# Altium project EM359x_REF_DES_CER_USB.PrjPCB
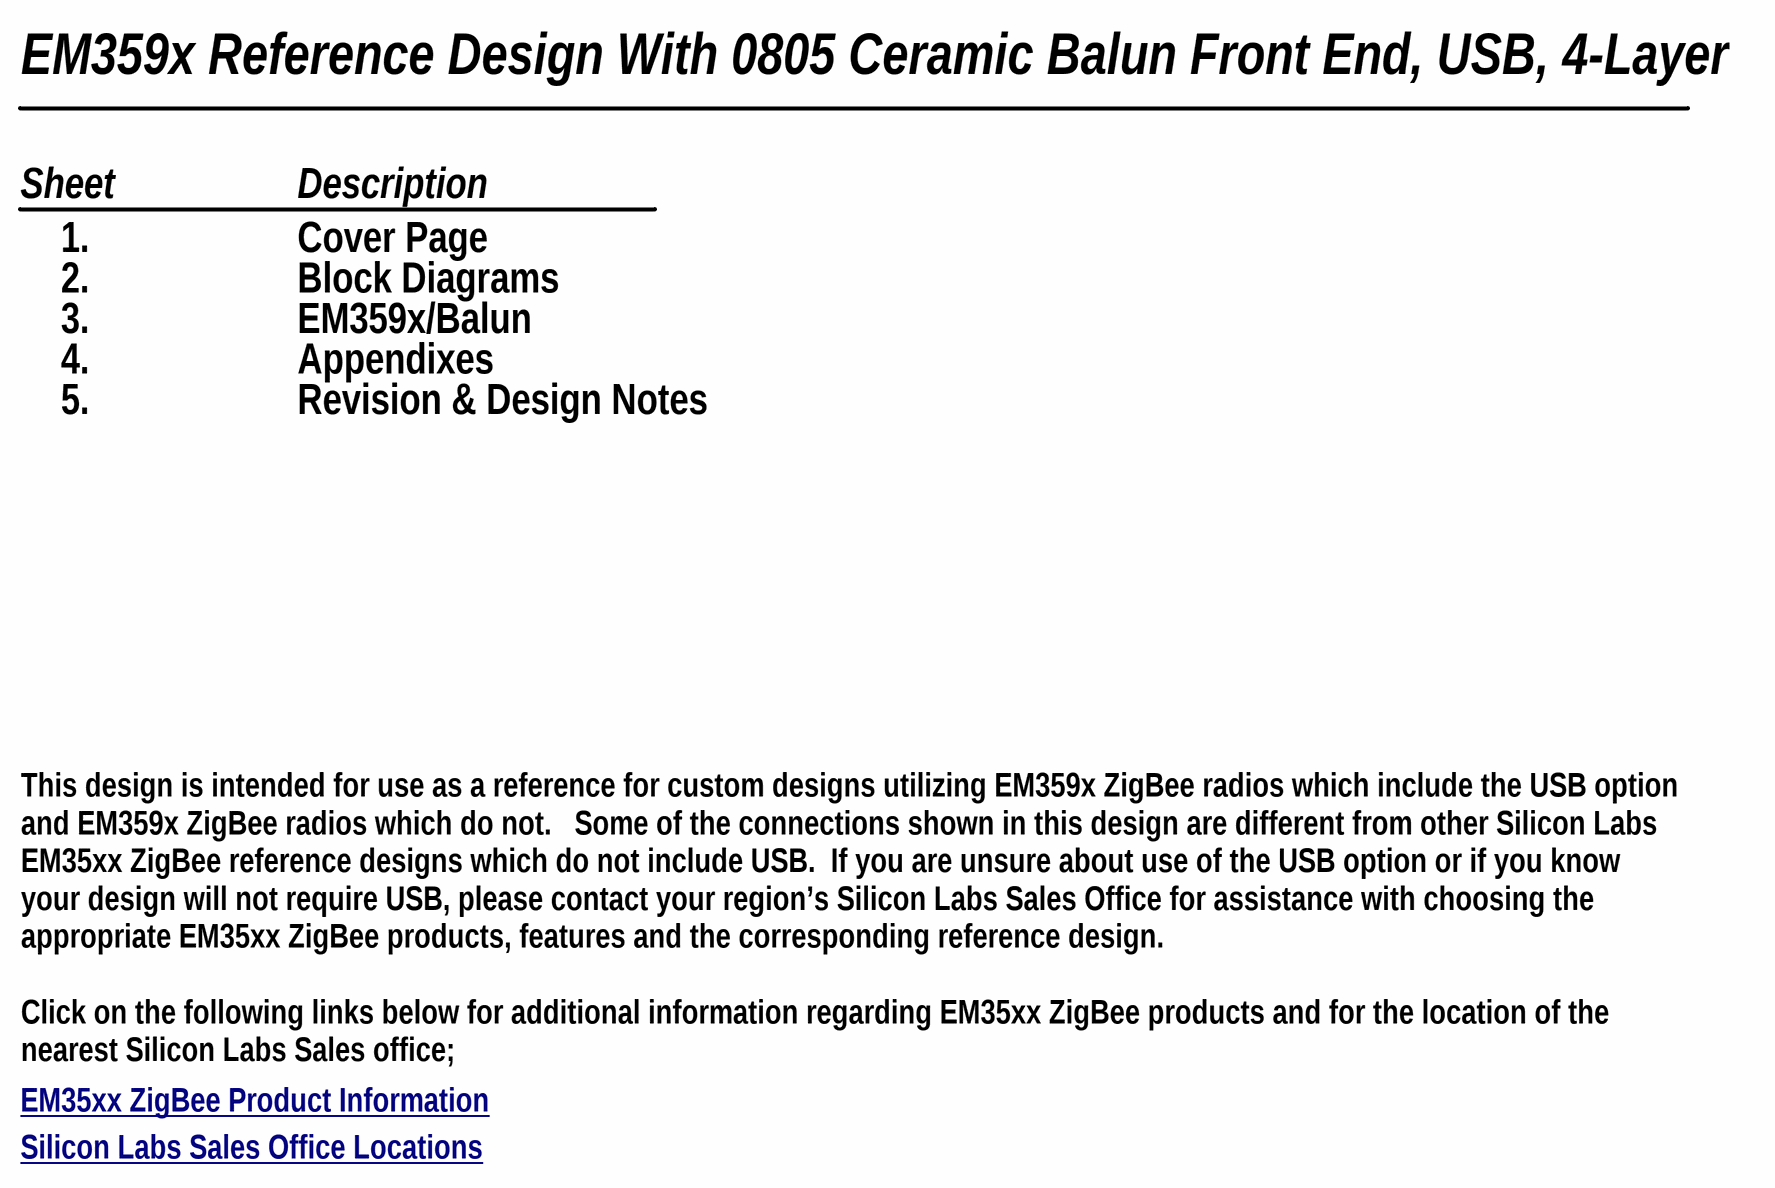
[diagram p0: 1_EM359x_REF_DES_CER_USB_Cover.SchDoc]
Board No: EM359x_REF_DES_CER_USB; Board Rev: A0; ClassName: PCB Only; Company Address 1: 343 Congress St; Company Address 2: 4th Floor; Company Address 3: Boston, MA 02210; Company Design Group: MCU & Wireless WMN Support; Company Tel: 617-951-0200; Company Web Site: www.silabs.com; Title: EM359x Ref Des, Ceramic Balun, USB, 4-layer
5 sheets, 70 parts. Net scope: global (net labels, ports and power ports of the same name join across sheets).
Board file: EM359x_REF_DES_CER_USB.PcbDoc
Sheets:
  1_EM359x_REF_DES_CER_USB_Cover.SchDoc
  2_EM359x_REF_DES_CER_USB_Block.SchDoc
  3_EM359x_REF_DES_CER_USB_Main.SchDoc
  4_EM359x_REF_DES_CER_USB_App.SchDoc
  5_EM359x_REF_DES_CER_USB_Rev_Notes.SchDoc

## Sheet 1_EM359x_REF_DES_CER_USB_Cover.SchDoc: EM359x/0805 Ceramic Balun W/USB Reference Design
size C; IsUserConfigurable: (Sheet Name); Organization: MCU & Wireless WMN Support; Address1: 343 Congress Street, 4th Fl,; Address2: Boston, MA 02210, USA; Address3: www.silabs.com; Address4: 617-951-0200; DocumentNumber: 130-0859-001; Revision: A0; SheetNumber: 1; SheetTotal: 5; SheetSize: C

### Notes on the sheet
- EM359x Reference Design With 0805 Ceramic Balun Front End, USB, 4-Layer
- Sheet
- 1.
- Description
- Cover Page
- 2.
- Block Diagrams
- 3.
- 4.
- EM359x/Balun
- Appendixes
- 5.
- Revision & Design Notes
- This design is intended for use as a reference for custom designs utilizing EM359x ZigBee radios which include the USB option and EM359x ZigBee radios which do not.   Some of the connections shown in this design are different from other Silicon Labs EM35xx ZigBee reference designs which do not include USB.  If you are unsure about use of the USB option or if you know your design will not require USB, please contact your region’s Silicon Labs Sales Office for assistance with choosing the appropriate EM35xx ZigBee products, features and the corresponding reference design.
  Click on the following links below for additional information regarding EM35xx ZigBee products and for the location of the nearest Silicon Labs Sales office;
- EM35xx ZigBee Product Information <http://www.silabs.com/products/wireless/zigbee/Pages/default.aspx>
- Silicon Labs Sales Office Locations <http://www.silabs.com/buysample/pages/contact-sales.aspx>

## Sheet 2_EM359x_REF_DES_CER_USB_Block.SchDoc: EM359x/0805 Ceramic Balun W/USB Reference Design
size C; Organization: MCU & Wireless WMN Support; Address1: 343 Congress Street, 4th Fl,; Address2: Boston, MA 02210, USA; Address3: www.silabs.com; Address4: 617-951-0200; DocumentNumber: 130-0859-001; Revision: A0; SheetNumber: 2; SheetTotal: 5; SheetSize: C
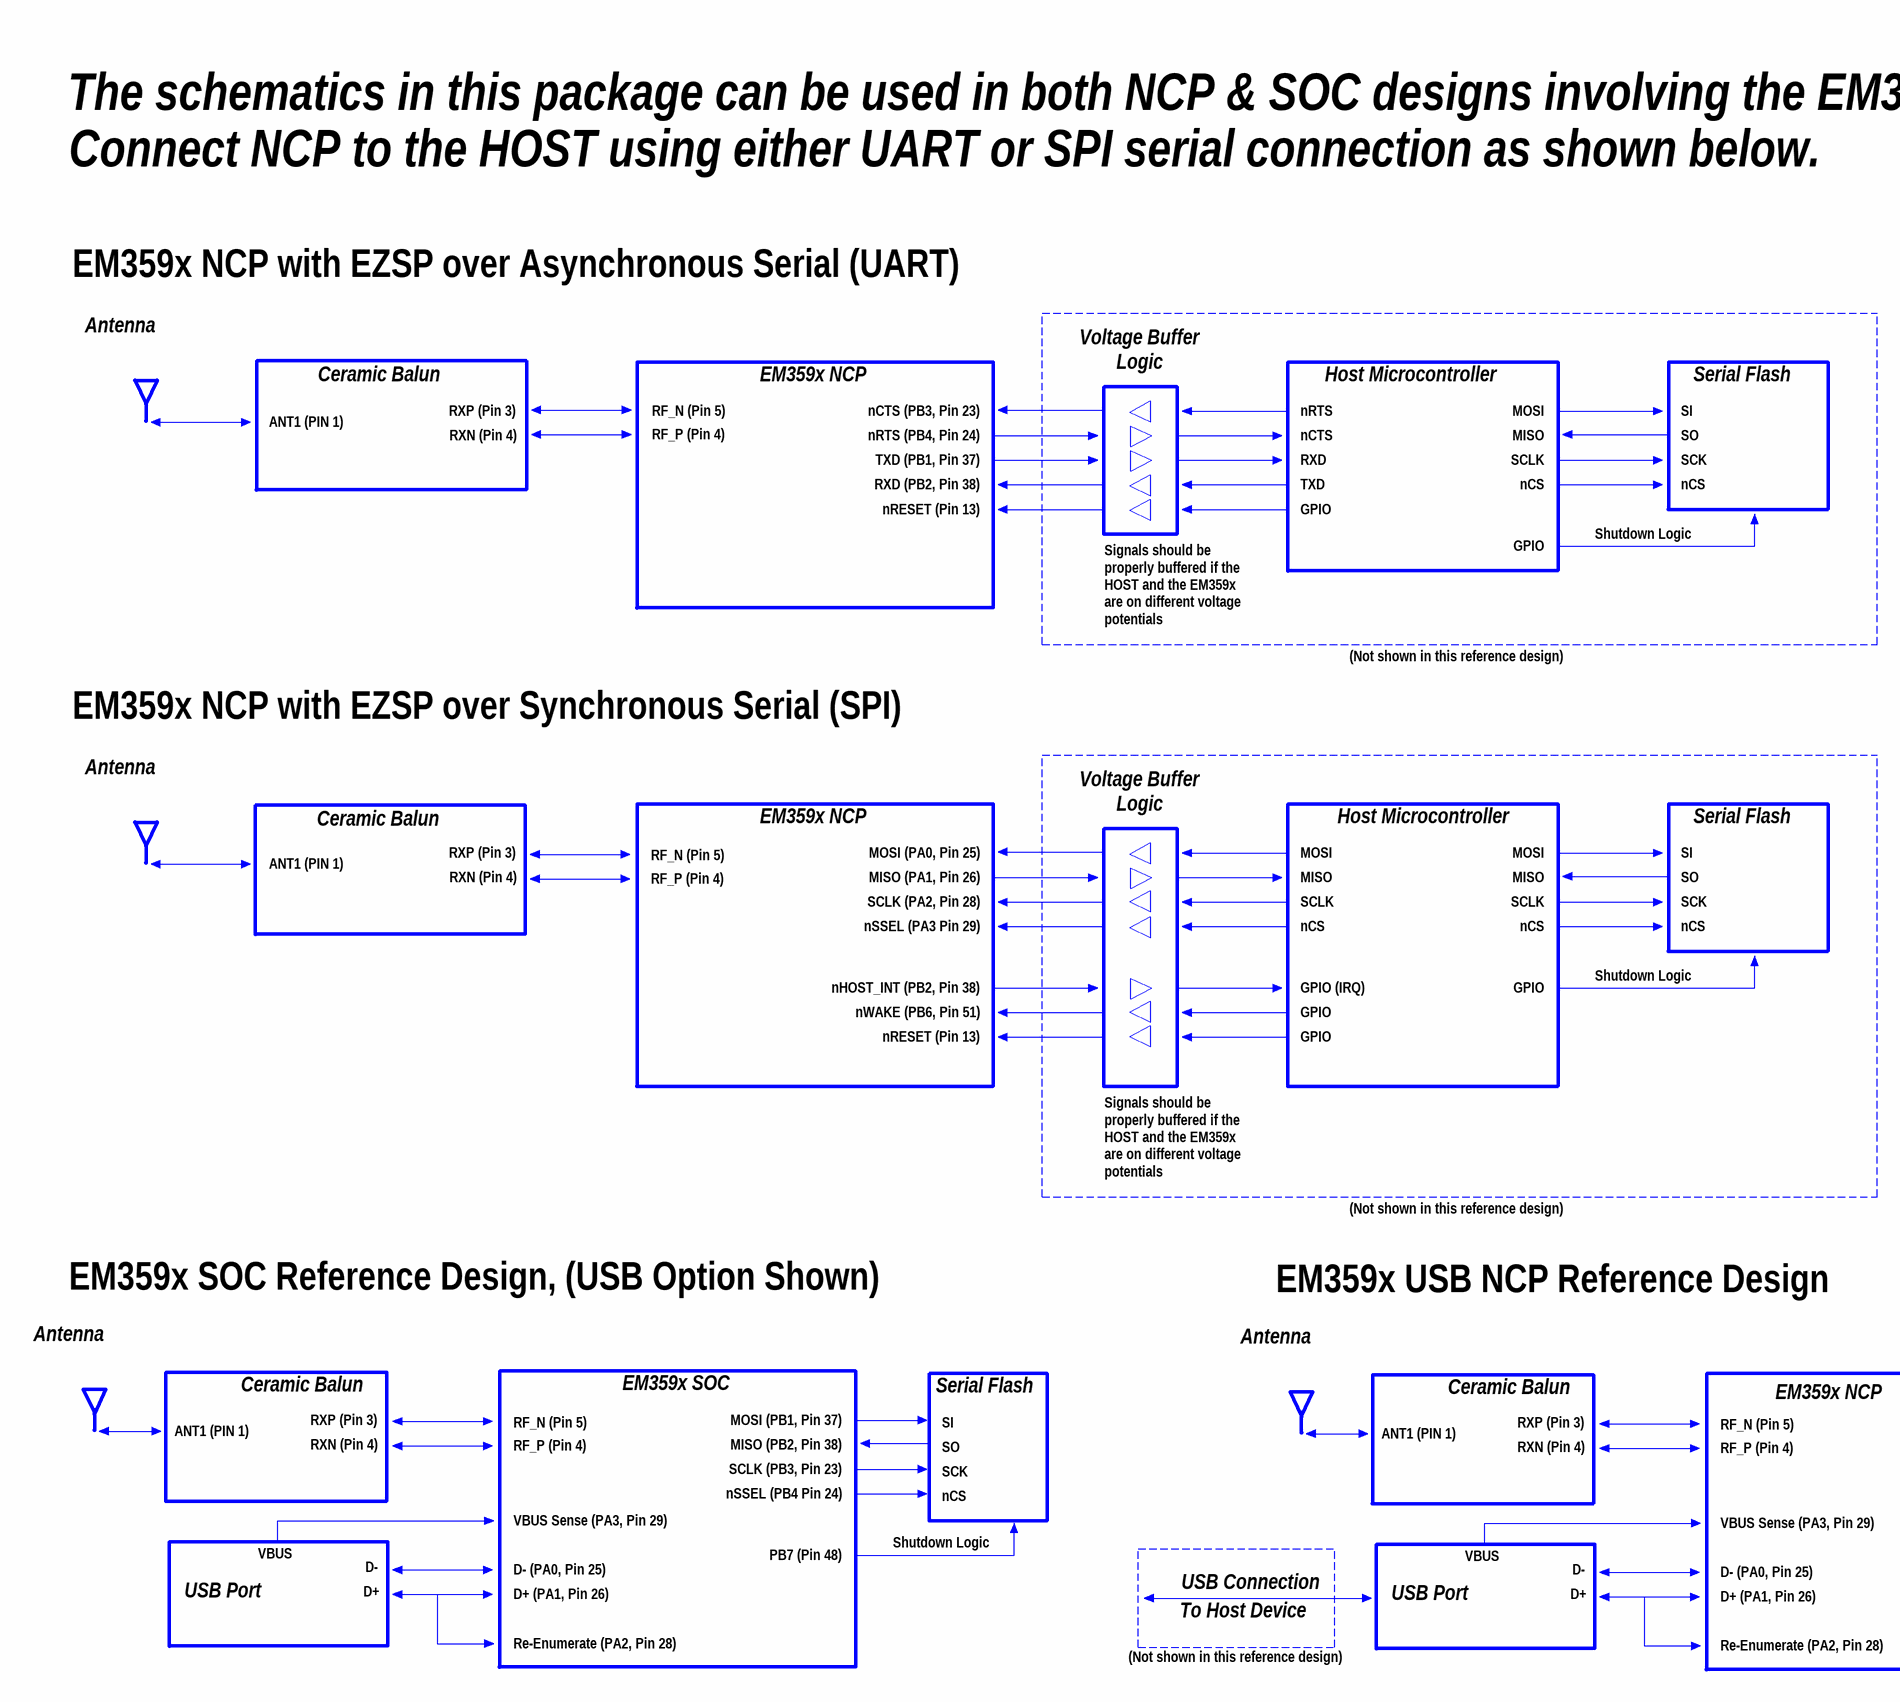
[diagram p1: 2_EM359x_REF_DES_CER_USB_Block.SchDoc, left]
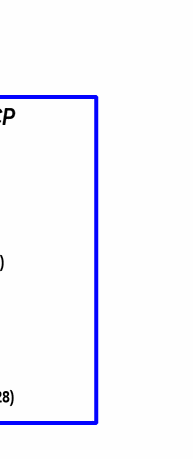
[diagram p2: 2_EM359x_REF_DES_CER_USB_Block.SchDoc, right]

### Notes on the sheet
- The schematics in this package can be used in both NCP & SOC designs involving the EM359x.
- Connect NCP to the HOST using either UART or SPI serial connection as shown below.
- EM359x NCP with EZSP over Asynchronous Serial (UART)
- Antenna
- Ceramic Balun
- EM359x NCP
- Voltage Buffer
- Logic
- Host Microcontroller
- Serial Flash
- ANT1 (PIN 1)
- RXP (Pin 3)
- RXN (Pin 4)
- RF_N (Pin 5)
- RF_P (Pin 4)
- nCTS (PB3, Pin 23)
- nRTS (PB4, Pin 24)
- nRTS
- nCTS
- MOSI
- MISO
- SI
- SO
- TXD (PB1, Pin 37)
- RXD (PB2, Pin 38)
- nRESET (Pin 13)
- RXD
- TXD
- GPIO
- SCLK
- nCS
- SCK
- Shutdown Logic
- Signals should be properly buffered if the HOST and the EM359x are on different voltage potentials
- (Not shown in this reference design)
- EM359x NCP with EZSP over Synchronous Serial (SPI)
- MOSI (PA0, Pin 25)
- MISO (PA1, Pin 26)
- SCLK (PA2, Pin 28)
- nSSEL (PA3 Pin 29)
- nHOST_INT (PB2, Pin 38)
- GPIO (IRQ)
- nWAKE (PB6, Pin 51)
- EM359x SOC Reference Design, (USB Option Shown)
- EM359x USB NCP Reference Design
- EM359x SOC
- MOSI (PB1, Pin 37)
- MISO (PB2, Pin 38)
- SCLK (PB3, Pin 23)
- nSSEL (PB4 Pin 24)
- VBUS
- VBUS Sense (PA3, Pin 29)
- PB7 (Pin 48)
- USB Port
- D-
- D+
- D- (PA0, Pin 25)
- D+ (PA1, Pin 26)
- To Host Device
- USB Connection
- Re-Enumerate (PA2, Pin 28)

## Sheet 3_EM359x_REF_DES_CER_USB_Main.SchDoc: EM359x/0805 Ceramic Balun W/USB Reference Design
size C; Organization: MCU & Wireless WMN Support; Address1: 343 Congress Street, 4th Fl,; Address2: Boston, MA 02210, USA; Address3: www.silabs.com; Address4: 617-951-0200; DocumentNumber: 130-0859-001; Revision: A0; SheetNumber: 3; SheetTotal: 5; SheetSize: C
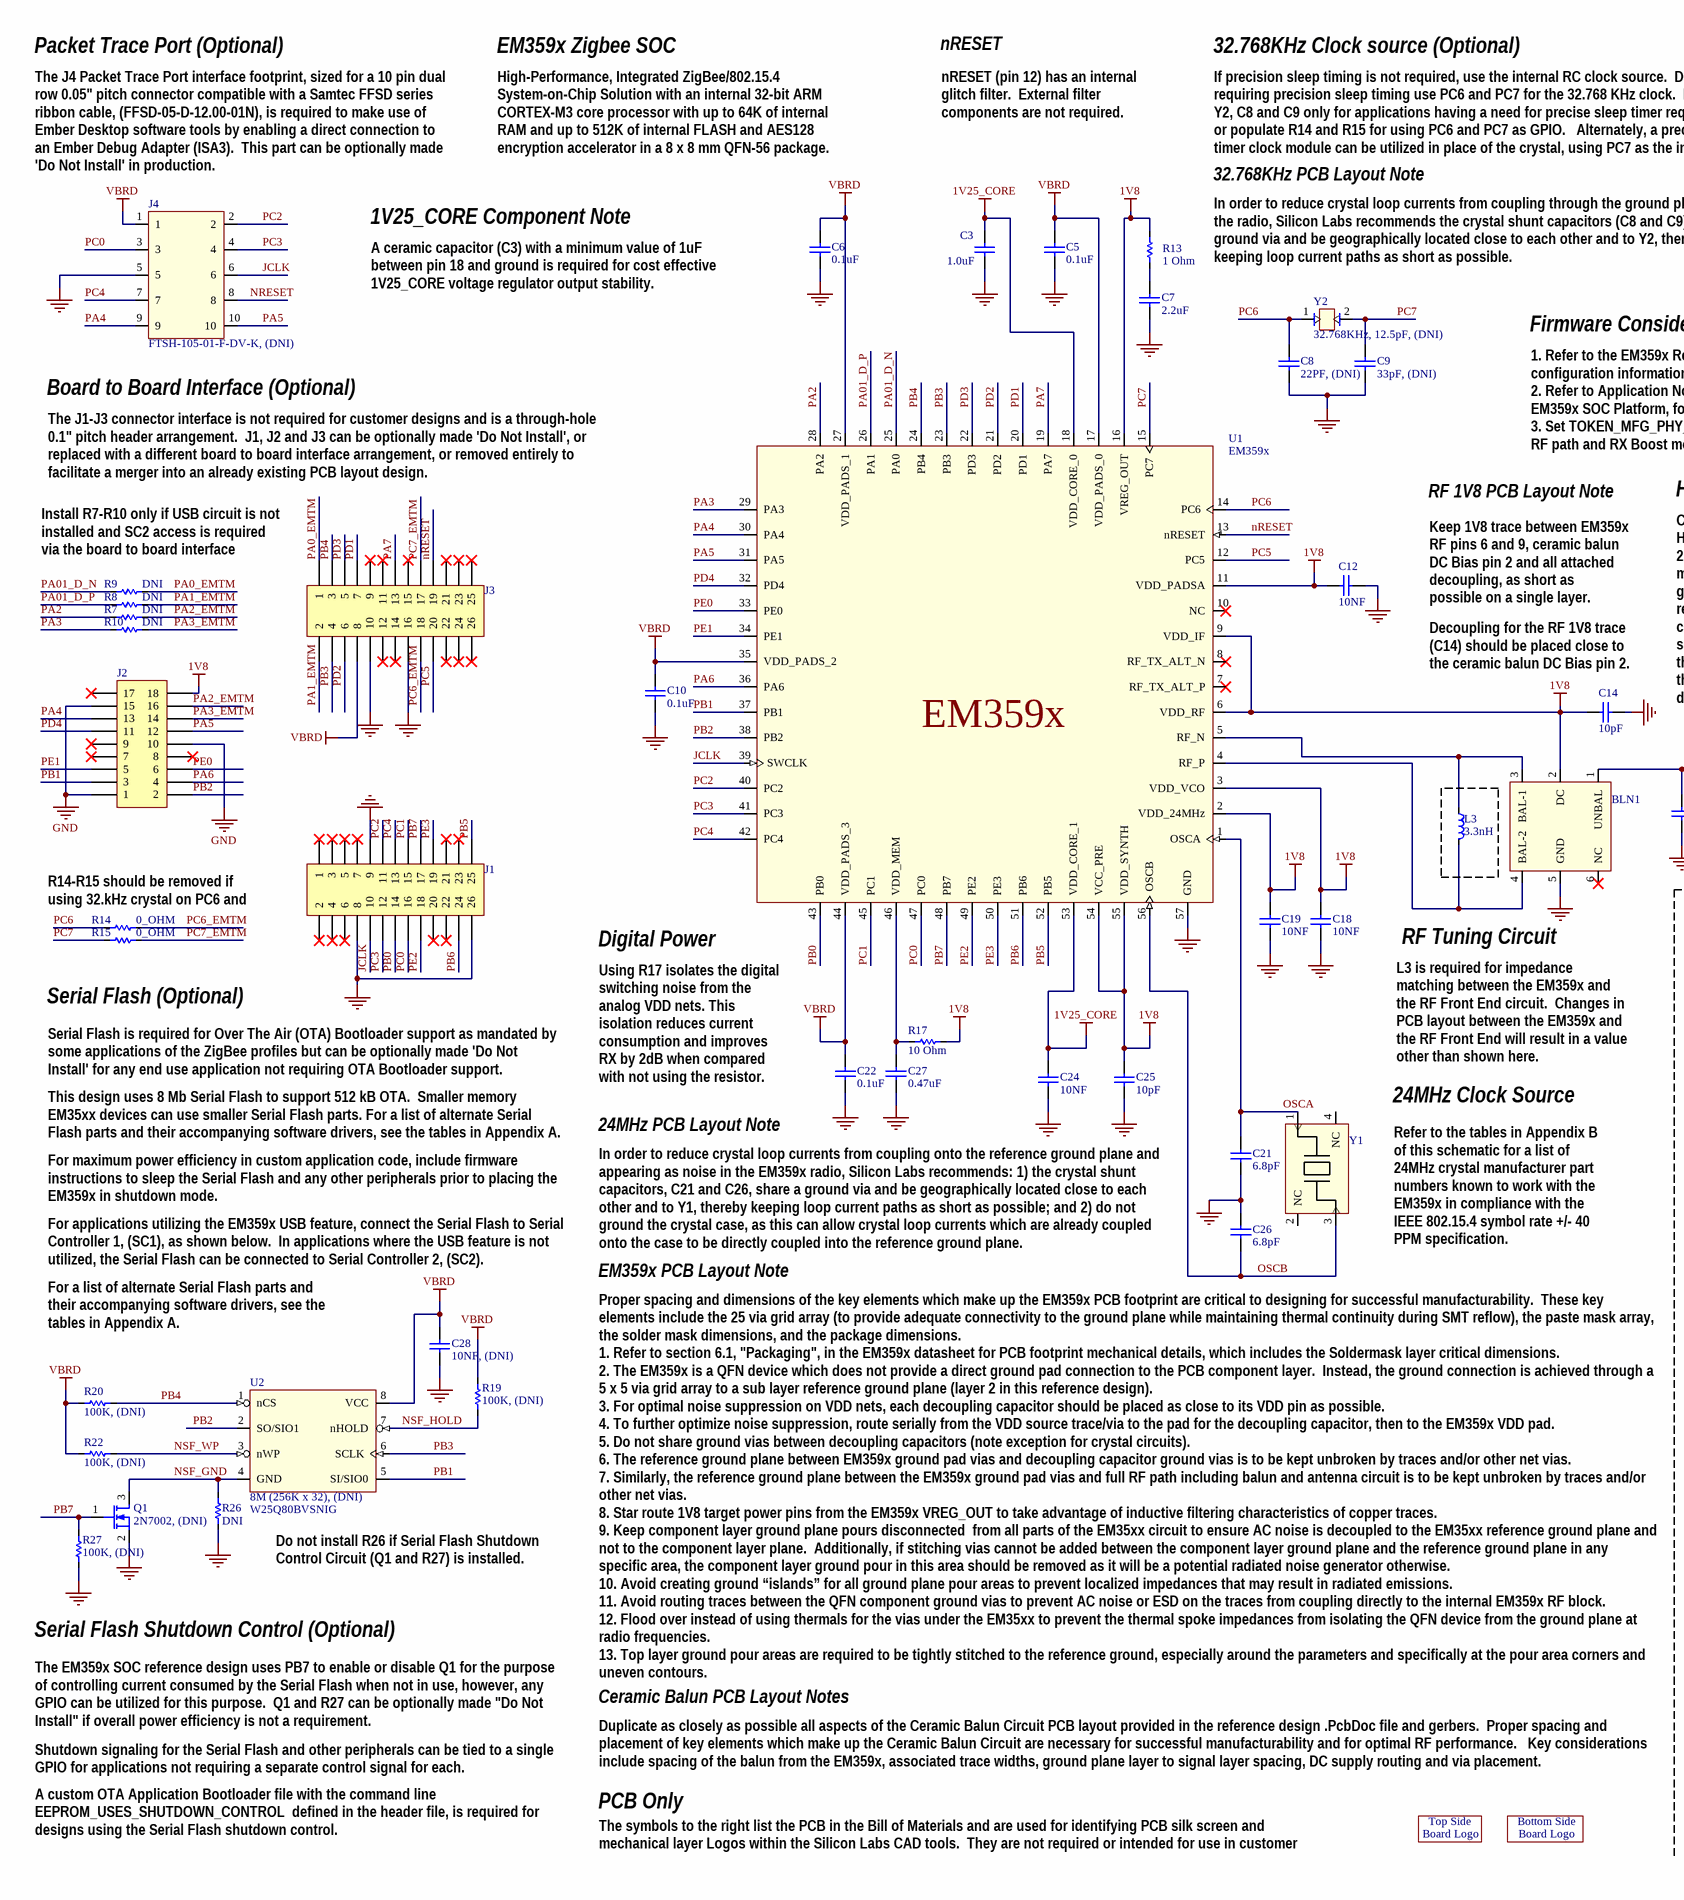
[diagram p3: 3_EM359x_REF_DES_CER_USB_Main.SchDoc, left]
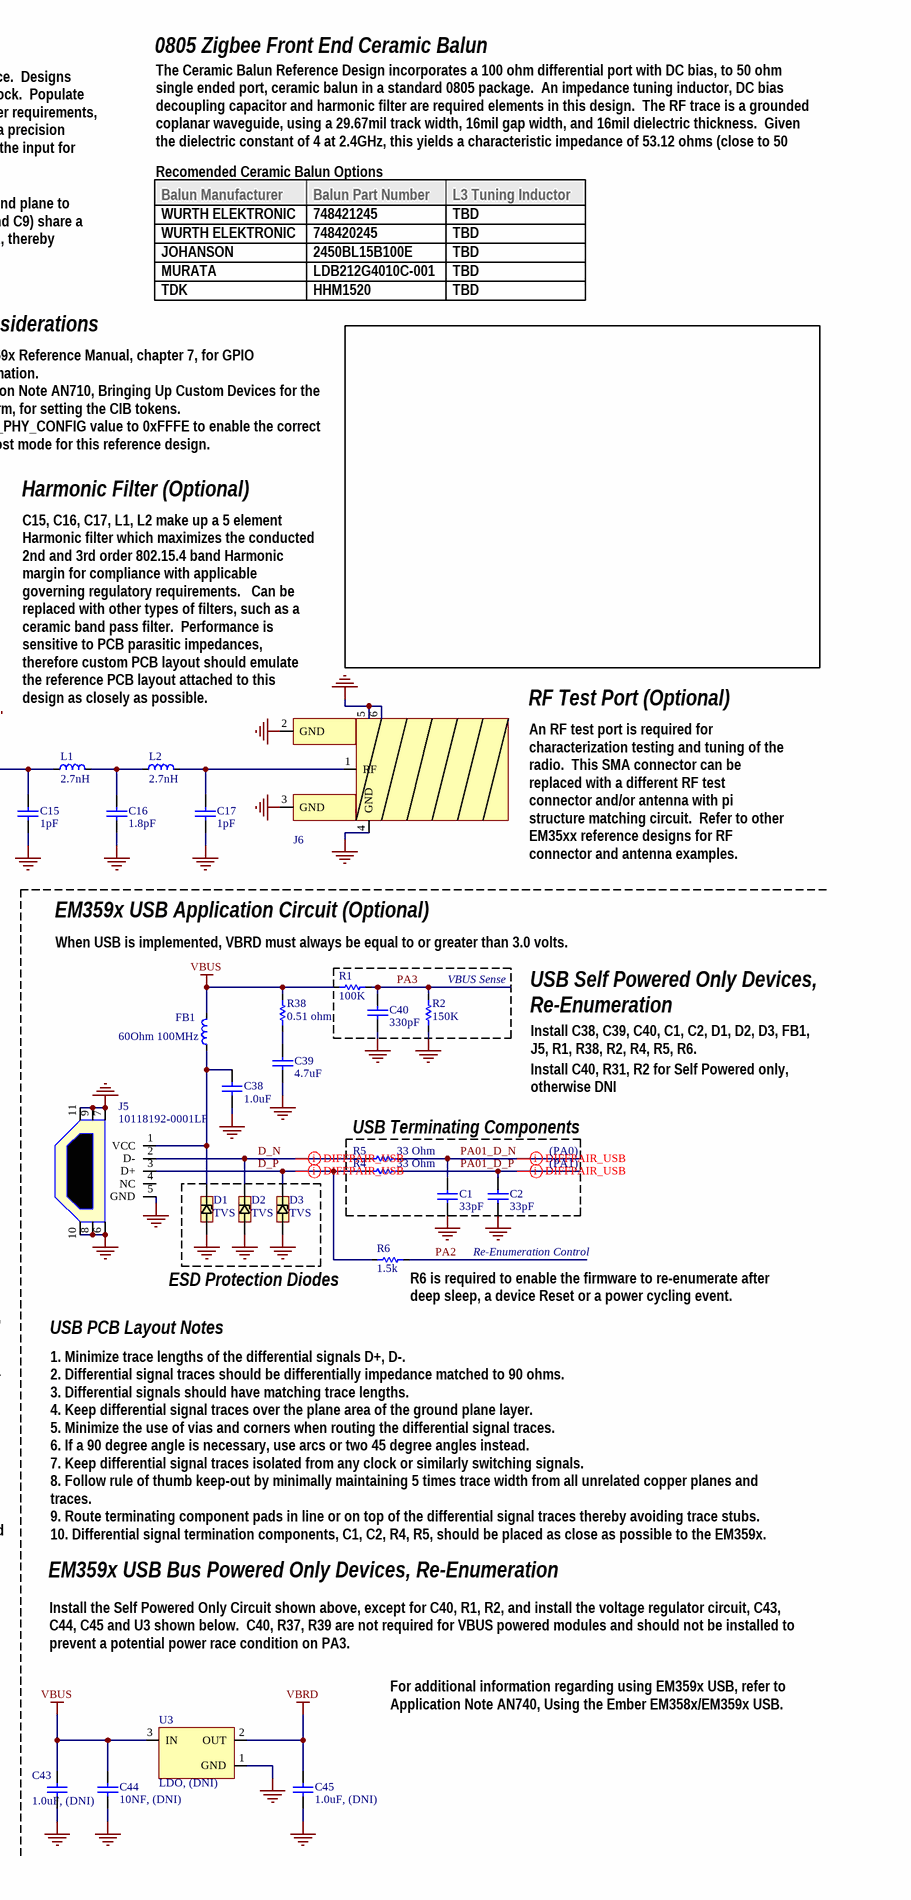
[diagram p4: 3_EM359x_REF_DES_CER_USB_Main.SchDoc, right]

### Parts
BLN1  CHIP MULTILAYER CERAMIC, 2.4 GHZ. 50/100 Ohm  [BLN_0805]  (value not drawn)
C1  33pF  [C_0402]
C2  33pF  [C_0402]
C3  1.0uF  [C_0603]
C5  0.1uF  [C_0402]
C6  0.1uF  [C_0402]
C7  2.2uF  [C_0603]
C8  22PF, (DNI)  [C_0402]
C9  33pF, (DNI)  [C_0402]
C10  0.1uF  [C_0402]
C12  10NF  [C_0402]
C14  10pF  [C_0402]
C15  1pF  [C_0402]
C16  1.8pF  [C_0402]
C17  1pF  [C_0402]
C18  10NF  [C_0402]
C19  10NF  [C_0402]
C21  6.8pF  [C_0402]
C22  0.1uF  [C_0402]
C24  10NF  [C_0402]
C25  10pF  [C_0402]
C26  6.8pF  [C_0402]
C27  0.47uF  [C_0402]
C28  10NF, (DNI)  [C_0402]
C38  1.0uF  [C_0603]
C39  4.7uF  [C_0603]
C40  330pF  [C_0402]
C43  1.0uF, (DNI)  [C_0603]
C44  10NF, (DNI)  [C_0402]
C45  1.0uF, (DNI)  [C_0603]
D1  TVS  [TVS_0402]
D2  TVS  [TVS_0402]
D3  TVS  [TVS_0402]
FB1  60Ohm 100MHz  [L_0603]
J1  HEADER 13 x 2  [HEADER-26-SUL-THRU-SHRD]  (value not drawn)
J2  HEADER 9 x 2  [HEADER-18-SUL-THRU-SHRD]  (value not drawn)
J3  HEADER 13 x 2  [HEADER-26-SUL-THRU-SHRD]  (value not drawn)
J4  FTSH-105-01-F-DV-K, (DNI)  [610-0019-000]
J5  10118192-0001LF  [FCI_10118192-0001LF]
J6  SMA_JACK_SMD  [SMA_WIDE]  (value not drawn)
L1  2.7nH  [L_0402]
L2  2.7nH  [L_0402]
L3  3.3nH  [L_0603]
PCB1  EM359x Ceramic Balun 4 Layer Reference Design w/USB, SMA Connector, Corporate Logo  [710-0859-001]  (value not drawn)
PCB2  Bottom Silk Screen ID and RoHS Text  [710-0859-001_ROHS]  (value not drawn)  (no BOM)
Q1  2N7002, (DNI)  [SOT23-3L]
R1  100K  [R_0402]
R2  150K  [R_0402]
R4  33 Ohm  [R_0402]
R5  33 Ohm  [R_0402]
R6  1.5k  [R_0402]
R7  DNI  [R_0402]
R8  DNI  [R_0402]
R9  DNI  [R_0402]
R10  DNI  [R_0402]
R13  1 Ohm  [R_0402]
R14  0_OHM  [R_0402]
R15  0_OHM  [R_0402]
R17  10 Ohm  [R_0402]
R19  100K, (DNI)  [R_0402]
R20  100K, (DNI)  [R_0402]
R22  100K, (DNI)  [R_0402]
R26  value DNI  [R_0402]  (hidden comment: EMBER_RESISTOR.1)
R27  100K, (DNI)  [R_0402]
R38  0.51 ohm  [R_0402]
U1  EM359x  [EM359X]
U2  8M (256K x 32), (DNI)  PART_NUMBER: W25Q80BVSNIG  [SOIC127P600-8M]
U3  LDO, (DNI)  [TSOP95P280X90-3N]
Y1  24MHz  [ABM8]  (value not drawn)
Y2  32.768KHz, 12.5pF, (DNI)  [IL3X]

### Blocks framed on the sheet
VBUS Sense: C40 R1 R2
USB Terminating Components: C1 C2 R4 R5

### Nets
1V8: BLN1.2(DC) C12.1 C14.2 C18.1 C19.1 C25.1 J2.18 R13.1 R17.1 U1.2(VDD_24MHz) U1.3(VDD_VCO) U1.6(VDD_RF) U1.9(VDD_IF) U1.11(VDD_PADSA) U1.16(VREG_OUT) U1.54(VCC_PRE) U1.55(VDD_SYNTH)
1V25_CORE: C3.1 C24.1 U1.18(VDD_CORE_0) U1.53(VDD_CORE_1)
GND: BLN1.5(GND) C1.1 C2.1 C3.2 C5.2 C6.2 C7.2 C8.2 C9.2 C10.2 C12.2 C14.1 C15.2 C16.2 C17.2 C18.2 C19.2 C21.2 C22.2 C24.2 C25.2 C26.2 C27.2 C28.2 C38.2 C39.2 C40.2 C43.2 C44.2 C45.2 D1.1 D2.1 D3.1 J1.8 J1.9 J1.26 J2.1 J2.10 J2.15 J3.10 J3.16 J4.5 J5.5(GND) J5.6 J5.7 J5.8 J5.9 J5.10 J5.11 J6.2(GND) J6.3(GND) J6.4(GND) J6.5(GND) J6.6(GND) Q1.2(S) R2.2 R26.2 R27.2 U1.57(GND) U3.1(GND)
VBRD: C5.1 C6.1 C10.1 C22.1 C28.1 C45.1 J3.8 J4.1 R19.2 R20.2 R22.2 U1.17(VDD_PADS_0) U1.27(VDD_PADS_1) U1.35(VDD_PADS_2) U1.44(VDD_PADS_3) U2.8(VCC) U3.2(OUT)
VBUS: C43.1 C44.1 FB1.2 R1.2 R38.2 U3.3(IN)
D_N: D2.2 J5.2(D-) R5.2
D_P: D3.2 J5.3(D+) R4.2 R6.2
JCLK: J1.10 J4.6 U1.39(SWCLK)
NRESET: J3.19 J4.8 U1.13(nRESET)
NSF_GND: Q1.3(D) R26.1 U2.4(GND)
NSF_HOLD: R19.1 U2.7(nHOLD)
NSF_WP: R22.1 U2.3(nWP)
OSCA: C21.1 U1.1(OSCA) Y1.1(OSCB)
OSCB: C26.1 U1.56(OSCB) Y1.3(OSCA)
PA0_EMTM: J3.1 R9.1
PA01_D_N: C1.2 R5.1 R9.2 U1.25(PA0)
PA01_D_P: C2.2 R4.1 R8.2 U1.26(PA1)
PA1_EMTM: J3.2 R8.1
PA2: R6.1 R7.1 U1.28(PA2)
PA2_EMTM: J2.16 R7.2
PA3: C40.1 R1.1 R2.1 R10.2 U1.29(PA3)
PA3_EMTM: J2.14 R10.1
PA4: J2.13 J4.9 U1.30(PA4)
PA5: J2.12 J4.10 U1.31(PA5)
PA6: J2.4 U1.36(PA6)
PA7: J3.13 U1.19(PA7)
PB0: J1.14 U1.43(PB0)
PB1: J2.3 U1.37(PB1) U2.5(SI/SIO0)
PB2: J2.2 U1.38(PB2) U2.2(SO/SIO1)
PB3: J3.4 U1.23(PB3) U2.6(SCLK)
PB4: J3.3 R20.1 U1.24(PB4) U2.1(nCS)
PB5: J1.25 U1.52(PB5)
PB6: J1.24 U1.51(PB6)
PB7: J1.17 Q1.1(G) R27.1 U1.48(PB7)
PC0: J1.16 J4.3 U1.47(PC0)
PC1: J1.15 U1.45(PC1)
PC2: J1.11 J4.2 U1.40(PC2)
PC3: J1.12 J4.4 U1.41(PC3)
PC4: J1.13 J4.7 U1.42(PC4)
PC5: J3.20 U1.12(PC5)
PC6: C8.1 R14.1 U1.14(PC6) Y2.1
PC6_EMTM: J3.18 R14.2
PC7: C9.1 R15.1 U1.15(PC7) Y2.2
PC7_EMTM: J3.17 R15.2
PD1: J3.7 U1.20(PD1)
PD2: J3.6 U1.21(PD2)
PD3: J3.5 U1.22(PD3)
PD4: J2.11 U1.32(PD4)
PE0: J2.6 U1.33(PE0)
PE1: J2.5 U1.34(PE1)
PE2: J1.18 U1.49(PE2)
PE3: J1.19 U1.50(PE3)
NetBLN1_1: BLN1.1(UNBAL) C15.1 L1.1
NetBLN1_3: BLN1.3(BAL-1) L3.1 U1.5(RF_N)
NetBLN1_4: BLN1.4(BAL-2) L3.2 U1.4(RF_P)
NetC7_1: C7.1 R13.2
NetC16_1: C16.1 L1.2 L2.1
NetC17_1: C17.1 J6.1(RF) L2.2
NetC27_1: C27.1 R17.2 U1.46(VDD_MEM)
NetC38_1: C38.1 D1.2 FB1.1 J5.1(VCC)
NetC39_1: C39.1 R38.1

Not connected (* = marked no-connect by the designer): BLN1 6(NC)*; J1 1* 2* 3* 4* 5* 6* 7* 20* 21* 22* 23*; J2 7* 8* 9* 17*; J3 9* 11* 12* 14* 15* 21* 22* 23* 24* 25* 26*; J5 4(NC); U1 7(RF_TX_ALT_P)* 8(RF_TX_ALT_N)* 10(NC)*; Y1 2(NC) 4(NC)

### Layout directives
rule Differential Pairs Routing [Pref Gap = 9mil    Min Gap  = 8mil    Max Gap  = 50mil]; rule Matched Net Lengths [Tolerance = 100mil]; differential pair; rule Width Constraint [Pref Width = 12mil    Min Width = 6mil    Max Width = 60mil]: D_N, D_P, PA01_D_N, PA01_D_P

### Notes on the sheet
- Packet Trace Port (Optional)
- EM359x Zigbee SOC
- nRESET
- 32.768KHz Clock source (Optional)
- 0805 Zigbee Front End Ceramic Balun
- nRESET (pin 12) has an internal glitch filter.  External filter components are not required.
- If precision sleep timing is not required, use the internal RC clock source.  Designs requiring precision sleep timing use PC6 and PC7 for the 32.768 KHz clock.  Populate Y2, C8 and C9 only for applications having a need for precise sleep timer requirements, or populate R14 and R15 for using PC6 and PC7 as GPIO.   Alternately, a precision timer clock module can be utilized in place of the crystal, using PC7 as the input for the clock.
- The Ceramic Balun Reference Design incorporates a 100 ohm differential port with DC bias, to 50 ohm single ended port, ceramic balun in a standard 0805 package.  An impedance tuning inductor, DC bias decoupling capacitor and harmonic filter are required elements in this design.  The RF trace is a grounded coplanar waveguide, using a 29.67mil track width, 16mil gap width, and 16mil dielectric thickness.  Given the dielectric constant of 4 at 2.4GHz, this yields a characteristic impedance of 53.12 ohms (close to 50 ohms).
- (near J4) The J4 Packet Trace Port interface footprint, sized for a 10 pin dual row 0.05" pitch connector compatible with a Samtec FFSD series ribbon cable, (FFSD-05-D-12.00-01N), is required to make use of Ember Desktop software tools by enabling a direct connection to an Ember Debug Adapter (ISA3).  This part can be optionally made 'Do Not Install' in production.
- High-Performance, Integrated ZigBee/802.15.4 System-on-Chip Solution with an internal 32-bit ARM CORTEX-M3 core processor with up to 64K of internal RAM and up to 512K of internal FLASH and AES128 encryption accelerator in a 8 x 8 mm QFN-56 package.
- 32.768KHz PCB Layout Note
- Recomended Ceramic Balun Options
- Balun Manufacturer
- Balun Part Number
- L3 Tuning Inductor
- 1V25_CORE Component Note
- In order to reduce crystal loop currents from coupling through the ground plane to the radio, Silicon Labs recommends the crystal shunt capacitors (C8 and C9) share a ground via and be geographically located close to each other and to Y2, thereby keeping loop current paths as short as possible.
- WURTH ELEKTRONIC
- JOHANSON
- MURATA
- 748421245
- 2450BL15B100E
- 748420245
- LDB212G4010C-001
- TBD
- A ceramic capacitor (C3) with a minimum value of 1uF between pin 18 and ground is required for cost effective 1V25_CORE voltage regulator output stability.
- Firmware Considerations
- TDK
- HHM1520
- Board to Board Interface (Optional)
- 1. Refer to the EM359x Reference Manual, chapter 7, for GPIO configuration information.
  2. Refer to Application Note AN710, Bringing Up Custom Devices for the EM359x SOC Platform, for setting the CIB tokens.
  3. Set TOKEN_MFG_PHY_CONFIG value to 0xFFFE to enable the correct RF path and RX Boost mode for this reference design.
- The J1-J3 connector interface is not required for customer designs and is a through-hole 0.1" pitch header arrangement.  J1, J2 and J3 can be optionally made 'Do Not Install', or replaced with a different board to board interface arrangement, or removed entirely to facilitate a merger into an already existing PCB layout design.
- RF 1V8 PCB Layout Note
- Harmonic Filter (Optional)
- Install R7-R10 only if USB circuit is not installed and SC2 access is required via the board to board interface
- Keep 1V8 trace between EM359x RF pins 6 and 9, ceramic balun DC Bias pin 2 and all attached decoupling, as short as possible on a single layer.
- (near C14) Decoupling for the RF 1V8 trace (C14) should be placed close to the ceramic balun DC Bias pin 2.
- (near J6) C15, C16, C17, L1, L2 make up a 5 element Harmonic filter which maximizes the conducted 2nd and 3rd order 802.15.4 band Harmonic margin for compliance with applicable governing regulatory requirements.   Can be replaced with other types of filters, such as a ceramic band pass filter.  Performance is sensitive to PCB parasitic impedances, therefore custom PCB layout should emulate the reference PCB layout attached to this design as closely as possible.
- RF Test Port (Optional)
- R14-R15 should be removed if using 32.kHz crystal on PC6 and PC7
- An RF test port is required for characterization testing and tuning of the radio.  This SMA connector can be replaced with a different RF test connector and/or antenna with pi structure matching circuit.  Refer to other EM35xx reference designs for RF connector and antenna examples.
- (near U1) Digital Power
- RF Tuning Circuit
- EM359x USB Application Circuit (Optional)
- When USB is implemented, VBRD must always be equal to or greater than 3.0 volts.
- Serial Flash (Optional)
- USB Self Powered Only Devices,
- Re-Enumeration
- Serial Flash is required for Over The Air (OTA) Bootloader support as mandated by some applications of the ZigBee profiles but can be optionally made 'Do Not Install' for any end use application not requiring OTA Bootloader support.
- Using R17 isolates the digital switching noise from the analog VDD nets. This isolation reduces current consumption and improves RX by 2dB when compared with not using the resistor.
- L3 is required for impedance matching between the EM359x and the RF Front End circuit.  Changes in PCB layout between the EM359x and the RF Front End will result in a value other than shown here.
- Install C38, C39, C40, C1, C2, D1, D2, D3, FB1, J5, R1, R38, R2, R4, R5, R6.
- Install C40, R31, R2 for Self Powered only, otherwise DNI
- This design uses 8 Mb Serial Flash to support 512 kB OTA.  Smaller memory EM35xx devices can use smaller Serial Flash parts. For a list of alternate Serial Flash parts and their accompanying software drivers, see the tables in Appendix A.
- 24MHz PCB Layout Note
- 24MHz Clock Source
- (PA0)
- For maximum power efficiency in custom application code, include firmware instructions to sleep the Serial Flash and any other peripherals prior to placing the EM359x in shutdown mode.
- (PA1)
- For applications utilizing the EM359x USB feature, connect the Serial Flash to Serial Controller 1, (SC1), as shown below.  In applications where the USB feature is not utilized, the Serial Flash can be connected to Serial Controller 2, (SC2).
- In order to reduce crystal loop currents from coupling onto the reference ground plane and appearing as noise in the EM359x radio, Silicon Labs recommends: 1) the crystal shunt capacitors, C21 and C26, share a ground via and be geographically located close to each other and to Y1, thereby keeping loop current paths as short as possible; and 2) do not ground the crystal case, as this can allow crystal loop currents which are already coupled onto the case to be directly coupled into the reference ground plane.
- EM359x PCB Layout Note
- Refer to the tables in Appendix B of this schematic for a list of 24MHz crystal manufacturer part numbers known to work with the EM359x in compliance with the IEEE 802.15.4 symbol rate +/- 40 PPM specification.
- (near R6) ESD Protection Diodes
- Re-Enumeration Control
- For a list of alternate Serial Flash parts and their accompanying software drivers, see the tables in Appendix A.
- USB PCB Layout Notes
- (near R6) R6 is required to enable the firmware to re-enumerate after deep sleep, a device Reset or a power cycling event.
- 1. Minimize trace lengths of the differential signals D+, D-.
  2. Differential signal traces should be differentially impedance matched to 90 ohms.
  3. Differential signals should have matching trace lengths.
  4. Keep differential signal traces over the plane area of the ground plane layer.
  5. Minimize the use of vias and corners when routing the differential signal traces.
  6. If a 90 degree angle is necessary, use arcs or two 45 degree angles instead.
  7. Keep differential signal traces isolated from any clock or similarly switching signals.
  8. Follow rule of thumb keep-out by minimally maintaining 5 times trace width from all unrelated copper planes and traces.
  9. Route terminating component pads in line or on top of the differential signal traces thereby avoiding trace stubs.
  10. Differential signal termination components, C1, C2, R4, R5, should be placed as close as possible to the EM359x.
  11. ESD and VBUS filter components should be placed as close as possible to the USB connector.
- Do not install R26 if Serial Flash Shutdown Control Circuit (Q1 and R27) is installed.
- EM359x USB Bus Powered Only Devices, Re-Enumeration
- Serial Flash Shutdown Control (Optional)
- Install the Self Powered Only Circuit shown above, except for C40, R1, R2, and install the voltage regulator circuit, C43, C44, C45 and U3 shown below.  C40, R37, R39 are not required for VBUS powered modules and should not be installed to prevent a potential power race condition on PA3.
- The EM359x SOC reference design uses PB7 to enable or disable Q1 for the purpose of controlling current consumed by the Serial Flash when not in use, however, any GPIO can be utilized for this purpose.  Q1 and R27 can be optionally made "Do Not Install" if overall power efficiency is not a requirement.
- Proper spacing and dimensions of the key elements which make up the EM359x PCB footprint are critical to designing for successful manufacturability.  These key elements include the 25 via grid array (to provide adequate connectivity to the ground plane while maintaining thermal continuity during SMT reflow), the paste mask array, the solder mask dimensions, and the package dimensions.
  1. Refer to section 6.1, "Packaging", in the EM359x datasheet for PCB footprint mechanical details, which includes the Soldermask layer critical dimensions.
  2. The EM359x is a QFN device which does not provide a direct ground pad connection to the PCB component layer.  Instead, the ground connection is achieved through a 5 x 5 via grid array to a sub layer reference ground plane (layer 2 in this reference design).
  3. For optimal noise suppression on VDD nets, each decoupling capacitor should be placed as close to its VDD pin as possible.
  4. To further optimize noise suppression, route serially from the VDD source trace/via to the pad for the decoupling capacitor, then to the EM359x VDD pad.
  5. Do not share ground vias between decoupling capacitors (note exception for crystal circuits).
  6. The reference ground plane between EM359x ground pad vias and decoupling capacitor ground vias is to be kept unbroken by traces and/or other net vias.
  7. Similarly, the reference ground plane between the EM359x ground pad vias and full RF path including balun and antenna circuit is to be kept unbroken by traces and/or other net vias.
  8. Star route 1V8 target power pins from the EM359x VREG_OUT to take advantage of inductive filtering characteristics of copper traces.
  9. Keep component layer ground plane pours disconnected  from all parts of the EM35xx circuit to ensure AC noise is decoupled to the EM35xx reference ground plane and not to the component layer plane.  Additionally, if stitching vias cannot be added between the component layer ground plane and the reference ground plane in any specific area, the component layer ground pour in this area should be removed as it will be a potential radiated noise generator otherwise.
  10. Avoid creating ground “islands” for all ground plane pour areas to prevent localized impedances that may result in radiated emissions.
  11. Avoid routing traces between the QFN component ground vias to prevent AC noise or ESD on the traces from coupling directly to the internal EM359x RF block.
  12. Flood over instead of using thermals for the vias under the EM35xx to prevent the thermal spoke impedances from isolating the QFN device from the ground plane at radio frequencies.
  13. Top layer ground pour areas are required to be tightly stitched to the reference ground, especially around the parameters and specifically at the pour area corners and uneven contours.
- Ceramic Balun PCB Layout Notes
- For additional information regarding using EM359x USB, refer to Application Note AN740, Using the Ember EM358x/EM359x USB.
- Shutdown signaling for the Serial Flash and other peripherals can be tied to a single GPIO for applications not requiring a separate control signal for each.
- Duplicate as closely as possible all aspects of the Ceramic Balun Circuit PCB layout provided in the reference design .PcbDoc file and gerbers.  Proper spacing and placement of key elements which make up the Ceramic Balun Circuit are necessary for successful manufacturability and for optimal RF performance.   Key considerations include spacing of the balun from the EM359x, associated trace widths, ground plane layer to signal layer spacing, DC supply routing and via placement.
- A custom OTA Application Bootloader file with the command line  EEPROM_USES_SHUTDOWN_CONTROL  defined in the header file, is required for designs using the Serial Flash shutdown control.
- PCB Only
- The symbols to the right list the PCB in the Bill of Materials and are used for identifying PCB silk screen and mechanical layer Logos within the Silicon Labs CAD tools.  They are not required or intended for use in customer designs.

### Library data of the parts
BLN1 = 566-0075-000: Balun 0805; Part Description: BALUN, CHIP MULTILAYER CERAMIC, 2.4 GHZ. 50/100 OHM, -40C TO 85C, 0805 (2012 METRIC); MANUFACTURER: WURTH ELEKTRONIC, JOHANSON TECHNOLOGY, MURATA, TDK; PART_NUMBER: 748421245, 2450BL15B100E, LDB212G4010C-001, HHM1520; Temperature Coefficient: -40C to 85C
C1 C2 = 550-0039-000: Part Description: CAPACITOR, CERAMIC, 33PF, +/-5%, 50V, -55C TO 125C, C0G, NP0, 0402 (1005 METRIC); MANUFACTURER: SAMSUNG ELECTRONICS; PART_NUMBER: CL05C330JB5NNNC; VOLTAGE: 50V; TOLERANCE: +/-5%; Temperature Coefficient: -55C to 125C, C0G, NP0
C3 C38 = 550-0033-000: Part Description: CAPACITOR, CERAMIC, 1.0UF, +/-10%, 10V, -55C TO 125C, X7R, 0603 (1608 METRIC); MANUFACTURER: TAIYO YUDEN LTD; PART_NUMBER: LMK107B7105KA-T; VOLTAGE: 10V; TOLERANCE: +/-10%; Temperature Coefficient: -55C to 125C, X7R
C5 C6 C10 C22 = 550-0034-000: Part Description: CAPACITOR, CERAMIC, 0.1UF, +/-10%, 6.3V, -55C TO 125C, X7R, 0402 (1005 METRIC); MANUFACTURER: MURATA; PART_NUMBER: GRM155R70J104KA01D; VOLTAGE: 6.3V; TOLERANCE: +/-10%; Temperature Coefficient: -55C to 125C, X7R
C7 = 550-0038-000: Part Description: CAPACITOR, CERAMIC, 2.2UF, +/-10%, 6.3V, -55C TO 125C, X7R, 0603 (1608 METRIC); MANUFACTURER: MURATA; PART_NUMBER: CL10B225KQ8NNNC; VOLTAGE: 6.3V; TOLERANCE: +/-10%; Temperature Coefficient: -55C to 125C, X7R
C8 = 550-2201-050-DNI: Part Description: CAPACITOR, CERAMIC, 22PF, (DNI), +/-5%, 50V, -55C TO 125C, 0402 (1005 METRIC); MANUFACTURER: MURATA; PART_NUMBER: GRM1555C1H220JA01D; VOLTAGE: 50V; TOLERANCE: +/-5%; Temperature Coefficient: -55C to 125C
C9 = 550-0039-000-DNI: Part Description: CAPACITOR, CERAMIC, 33PF, (DNI), +/-5%, 50V, -55C TO 125C, C0G, NP0, 0402 (1005 METRIC); MANUFACTURER: SAMSUNG ELECTRONICS; PART_NUMBER: CL05C330JB5NNNC; VOLTAGE: 50V; TOLERANCE: +/-5%; Temperature Coefficient: -55C to 125C, C0G, NP0
C12 C18 C19 C24 = 550-0036-000: Part Description: CAPACITOR, CERAMIC, 10NF, +/-10%, 6.3V, -55C TO 125C, X7R, 0402 (1005 METRIC); MANUFACTURER: MURATA; PART_NUMBER: GRM155R70J103KA01D; VOLTAGE: 6.3V; TOLERANCE: +/-10%; Temperature Coefficient: -55C to 125C, X7R
C14 = 550-1001-050: Part Description: CAPACITOR, CERAMIC, 10PF, +/-5%, 50V, -55C TO 125C, 0402 (1005 METRIC); MANUFACTURER: MURATA; PART_NUMBER: GRM1555C1H100JA01D; VOLTAGE: 50V; TOLERANCE: +/-5%; Temperature Coefficient: -55C to 125C
C15 C17 = 550-0040-000: Part Description: CAPACITOR, CERAMIC, 1PF, +/-0.25PF, 50V, -55C TO 125C, C0G, NP0, 0402 (1005 METRIC); MANUFACTURER: SAMSUNG ELECTRONICS; PART_NUMBER: CL05C010CB5NNNC; VOLTAGE: 50V; TOLERANCE: +/-0.25pF; Temperature Coefficient: -55C to 125C, C0G, NP0
C16 = 550-1P8A-050: Part Description: CAPACITOR, CERAMIC, 1.8PF, +/-0.25PF, 50V, -55C TO 125C, C0G, NP0, 0402 (1005 METRIC); VOLTAGE: 50V; TOLERANCE: +/-0.25pF; Temperature Coefficient: -55C to 125C, C0G, NP0
C21 C26 = 550-6P81-050: Part Description: CAPACITOR, 6.8PF, +/-0.25PF, 50V, NP0, 0402; MANUFACTURER: MURATA; PART_NUMBER: GRM1555C1H6R8CA01D; VOLTAGE: 50V; TOLERANCE: +/-0.25pF; Temperature Coefficient: -55C to 125C, C0G, NP0
C25 = 550-1001-050: Part Description: CAPACITOR, CERAMIC, 10PF, +/-5%, 50V, -55C TO 125C, 0402 (1005 METRIC); VOLTAGE: 50V; TOLERANCE: +/-5%; Temperature Coefficient: -55C to 125C
C27 = 550-0037-000: Part Description: CAPACITOR, CERAMIC, 0.47UF, +/- 10%, 6.3V, -55C TO 85C, X5R, 0402 (1005 METRIC); MANUFACTURER: MURATA; PART_NUMBER: GRM155R60J474KE19D; VOLTAGE: 6.3V; TOLERANCE: +/- 10%; Temperature Coefficient: -55C to 85C, X5R
C28 = 550-0036-000-DNI: Part Description: CAPACITOR, CERAMIC, 10NF, (DNI), +/-10%, 6.3V, -55C TO 125C, X7R, 0402 (1005 METRIC); MANUFACTURER: MURATA; PART_NUMBER: GRM155R70J103KA01D; VOLTAGE: 6.3V; TOLERANCE: +/-10%; Temperature Coefficient: -55C to 125C, X7R
C39 = 550-0041-000: Part Description: CAPACITOR, CERAMIC, 4.7UF, -20%_+80%, 10V, -30C TO 85C, Y5V, 0603 (1608 METRIC); MANUFACTURER: MURATA; PART_NUMBER: GRM188F51A475ZE20D; VOLTAGE: 10V; TOLERANCE: -20%_+80%; Temperature Coefficient: -30C to 85C, Y5V
C40 = 550-0042-000: Part Description: CAPACITOR, CERAMIC, 330PF, +/- 10%, 50V, -55C TO 125C, X7R, 0402 (1005 METRIC); MANUFACTURER: YAGEO; PART_NUMBER: CC0402KRX7R9BB331; VOLTAGE: 50V; TOLERANCE: +/- 10%; Temperature Coefficient: -55C to 125C, X7R
C43 C45 = 550-0033-000-DNI: Part Description: CAPACITOR, CERAMIC, 1.0UF, (DNI), +/-10%, 10V, -55C TO 125C, X7R, 0603 (1608 METRIC); MANUFACTURER: TAIYO YUDEN LTD; PART_NUMBER: LMK107B7105KA-T; VOLTAGE: 10V; TOLERANCE: +/-10%; Temperature Coefficient: -55C to 125C, X7R
C44 = 550-0035-000-DNI: Part Description: CAPACITOR, CERAMIC, 10NF, (DNI), +/-10%, 10V, -55C TO 125C, X7R, 0402 (1005 METRIC); MANUFACTURER: KEMET; PART_NUMBER: C0402C103K8RACTU; TOLERANCE: +/-10%; VOLTAGE: 10V; Temperature Coefficient: -55C to 125C, X7R
D1-D3 = 545-0062-000: Part Description: DIODE, TVS, 45W, 5V, SOD-882; VOLTAGE: 5V; POWER: 45W
FB1 = 566-0001-000: *; Part Description: FERRITE BEAD, 60 OHM, 500MA, 0603 SMD; MANUFACTURER: MURATA; PART_NUMBER: BLM18PG600SN1D; Current Rating: 500MA
J1 J3 = 610-7116-000: Part Description: CONNECTOR, HEADER, FEMALE, 26 POSITION, .1" DUAL, GOLD, THROUGH HOLE; MANUFACTURER: SULLINS ELECTRONICS; PART_NUMBER: PPPC132LFBN-RC
J2 = 610-7112-000: Part Description: CONNECTOR, HEADER, FEMALE, 18 POSITION, .1" DUAL, GOLD, THROUGH HOLE; MANUFACTURER: SULLINS ELECTRONICS; PART_NUMBER: PPPC092LFBN-RC
J4 = 610-0045-000-DNI: CONNECTOR, HEADER, SHROUDED, 10 POSITION, DUAL ROW, VERTICAL, 0.050"; Part Description: CONNECTOR, HEADER, FTSH-105-01-F-DV-K, (DNI), 10 POSITION, DUAL ROW, VERTICAL, 0.050"
J5 = 610-0105-000: Part Description: CONNECTOR, USB, 10118192-0001LF, MICRO B, SMD; MANUFACTURER: FCI
J6 = 610-0093-000: Part Description: CONNECTOR,  JACK, END LAUNCH-WIDE, PCB, GOLD, SMA; MANUFACTURER: Emerson Network Power; PART_NUMBER: 142-0701-851
L1 L2 = 566-2N7W-000: Design Placeholder; Part Description: INDUCTOR, WIRE WOUND, 2.7NH, +/-0.2NH, 850MA, -55C TO 125C, 0402 (1005 METRIC); Current Rating: 850mA; TOLERANCE: +/-0.2nH; Temperature Coefficient: -55C to 125C
L3 = 566-3N3S-000: Design Placeholder; Part Description: INDUCTOR, METAL FILM, 3.3NH, +/-0.3NH, 500MA, -40C TO 85C, 0603 (1608 METRIC); Current Rating: 500MA; TOLERANCE: +/-0.3NH; Temperature Coefficient: -40C to 85C
PCB1 = 710-0859-001: PCB BoM ID and Top Side Silk Screen Identifier; Part Description: MECHANICAL, PCB, EM359X CERAMIC BALUN 4 LAYER REFERENCE DESIGN W/USB, SMA CONNECTOR, CORPORATE LOGO
PCB2 = 710-0859-001_ROHS: Bottom Side Silk Screen Identifier; Part Description: MECHANICAL, PCB, EM359X CERAMIC BALUN 4 LAYER REFERENCE DESIGN W/USB, SMA CONNECTOR, BOTTOM SIDE CORPORATE LOGO W/ROHS LOGO; VALUE: EM359x Ceramic Balun 4 Layer Reference Design w/USB, SMA Connector, Bottom Side Corporate Logo w/ROHS logo
Q1 = 545-0047-000-DNI: MOSFET N-Channel; Part Description: MOSFET, 2N7002, (DNI), 300MA, 830MW, 60V, TO-236-3, SC-59, SOT-23-3; VOLTAGE: 60V; POWER: 830mW; Current Rating: 300mA
R1 = 555-1045-016: Part Description: RESISTOR, THICK FILM, 100K, +/-5%, 0.1W, 1/10W, 0402 (1005 METRIC); MANUFACTURER: PANASONIC ECG; PART_NUMBER: ERJ-2GEJ104X; POWER: 0.1W, 1/10W; TOLERANCE: +/-5%; Temperature Coefficient: +/-200ppm/C
R2 = 555-150K-016: Part Description: RESISTOR, THICK FILM, 150K, +/-1%, 1/16W, 0402 (1005 METRIC); MANUFACTURER: SAMSUNG ELECTRONICS; PART_NUMBER: RC1005J154CS; POWER: 1/16W; TOLERANCE: +/-1%; Temperature Coefficient: +/-100ppm/C
R4 R5 = 555-33R1-010: Part Description: RESISTOR, CHIP, 33 OHM, +/-1%, 0.1W, 1/10W, 0402; MANUFACTURER: PANASONIC ECG; PART_NUMBER: ERJ-2RKF33R0X; TOLERANCE: +/-1%; POWER: 0.1W, 1/10W
R6 = 555-1521-016: Part Description: RESISTOR, 1.5K OHM, 1%, 1/16W, 0402; POWER: 1/16W; TOLERANCE: +/-1%; Temperature Coefficient: +/-100ppm/C
R7-R10 R26 = 555-0000-DNI: Part Description: RESISTOR, 0402, DO NOT INSTALL
R13 = 555-1R05-016: Part Description: RESISTOR, THICK FILM, 1 OHM, +/-5%, 0.1W, 1/10W, 0402 (1005 METRIC); POWER: 0.1W, 1/10W; TOLERANCE: +/-5%; Temperature Coefficient: -100/ +600ppm/C
R14 R15 = 555-0000-000: Part Description: RESISTOR, THICK FILM, 0_OHM, JUMPER, 1/10W, 0402 (1005 METRIC); POWER: 1/10W; TOLERANCE: Jumper; Temperature Coefficient: -100/ +600ppm/C
R17 = 555-1001-010: Part Description: RESISTOR, THICK FILM, 10 OHM, +/-1%, 0.1W, 1/10W, 0402 (1005 METRIC); POWER: 0.1W, 1/10W; TOLERANCE: +/-1%; Temperature Coefficient: +/-100ppm/C
R19 R27 = 555-1045-016-DNI: Part Description: RESISTOR, THICK FILM, 100K, (DNI), +/-5%, 0.1W, 1/10W, 0402 (1005 METRIC); MANUFACTURER: PANASONIC ECG; PART_NUMBER: ERJ-2GEJ104X; POWER: 0.1W, 1/10W; TOLERANCE: +/-5%; Temperature Coefficient: +/-200ppm/C
R20 R22 = 555-1045-016-DNI: Part Description: RESISTOR, THICK FILM, 100K, (DNI), +/-5%, 0.1W, 1/10W, 0402 (1005 METRIC); MANUFACTURER: PANASONIC ECG; PART_NUMBER: ERJ-2GEJ104X; TOLERANCE: +/-5%; POWER: 0.1W, 1/10W; Temperature Coefficient: +/-200ppm/C
R38 = 555-0017-000: Part Description: RESISTOR, THICK FILM, 0.51 OHM, +/-1%, 0.167W, 1/6W, 0402 (1005 METRIC); MANUFACTURER: PANASONIC ECG; PART_NUMBER: ERJ-2BQFR51X; POWER: 0.167W, 1/6W; Temperature Coefficient: +/-250ppm/C; TOLERANCE: +/-1%
U1 = 540-0359-056: IC, EM359X, ZIGBEE/802.15.4 RF SOLUTION, ARM CORTEX-M3, 64kB RAM, 512kB FLASH, QFN-56; Part Description: IC, COMMUNICATIONS, EM359X, -40C TO 85C, SOC, ZIGBEE/802.15.4 RF TRANSCEIVER, ARM CORTEX-M3, TO 12 - 64K RAM, 128 - 512K FLASH, 56-QFN; MANUFACTURER: SILICON LABS
U2 = 510-1032-000-DNI: IC - MEMORY, IC - MEMORY, SERIAL FLASH, 2M (256K X 8), 2.7 V - 3.6 V, -40C  85C, 8-SOIC (0.154", 3.90MM WIDTH); Part Description: IC - PROGRAMMABLE MEMORY - BLANK, SERIAL FLASH, 8M (256K X 32), (DNI), 2.7 V - 3.6 V, -40C  85C, 8-SOIC (0.154", 3.90MM WIDTH); MANUFACTURER: Winbond
U3 = 500-0089-000-DNI: PART_NUMBER: AAT3220IGY-3.3-T1; Part Description: IC, LDO, (DNI), 3.3V, 150MA, -40C TO 85C, SC59; MANUFACTURER: SKYWORKS INC
Y1 = 565-2400-004: Crystal, 3.2 mm x 2.5 mm x 0.7 mm, ABM8; Part Description: OSCILLATOR, CRYSTAL, 24MHZ, 10PF, +/-40PPM OVERALL, -40C +125C, 3.2 MM X 2.5 MM X 0.7 MM, ABM8; MANUFACTURER: ABRACON; PART_NUMBER: ABM8X-101-24.000MHz-T; Value: 24MHz, 10pF; TOLERANCE: +/-40ppm Overall; Temperature Coefficient: -40C +125C
Y2 = 565-3271-001-DNI: Part Description: OSCILLATOR, CRYSTAL, 32.768KHZ, 12.5PF, (DNI), +/-20PPM, -40C TO 85C, 2-SMD; MANUFACTURER: ABRACON, FOX CRYSTALS, ILSI AMERICA, ILSI AMERICA; PART_NUMBER: ABS07-32.768KHz-T, FX135A-327, IL3X-HX5-12.5-32.768KHz, IL3X-BX5-12.5-32.768KHz; TOLERANCE: +/-20ppm; Temperature Coefficient: -40C to 85C

## Sheet 4_EM359x_REF_DES_CER_USB_App.SchDoc: EM359x/0805 Ceramic Balun W/USB Reference Design
size C; Organization: MCU & Wireless WMN Support; Address1: 343 Congress Street, 4th Fl,; Address2: Boston, MA 02210, USA; Address3: www.silabs.com; Address4: 617-951-0200; DocumentNumber: 130-0859-001; Revision: A0; SheetNumber: 4; SheetTotal: 5; SheetSize: C
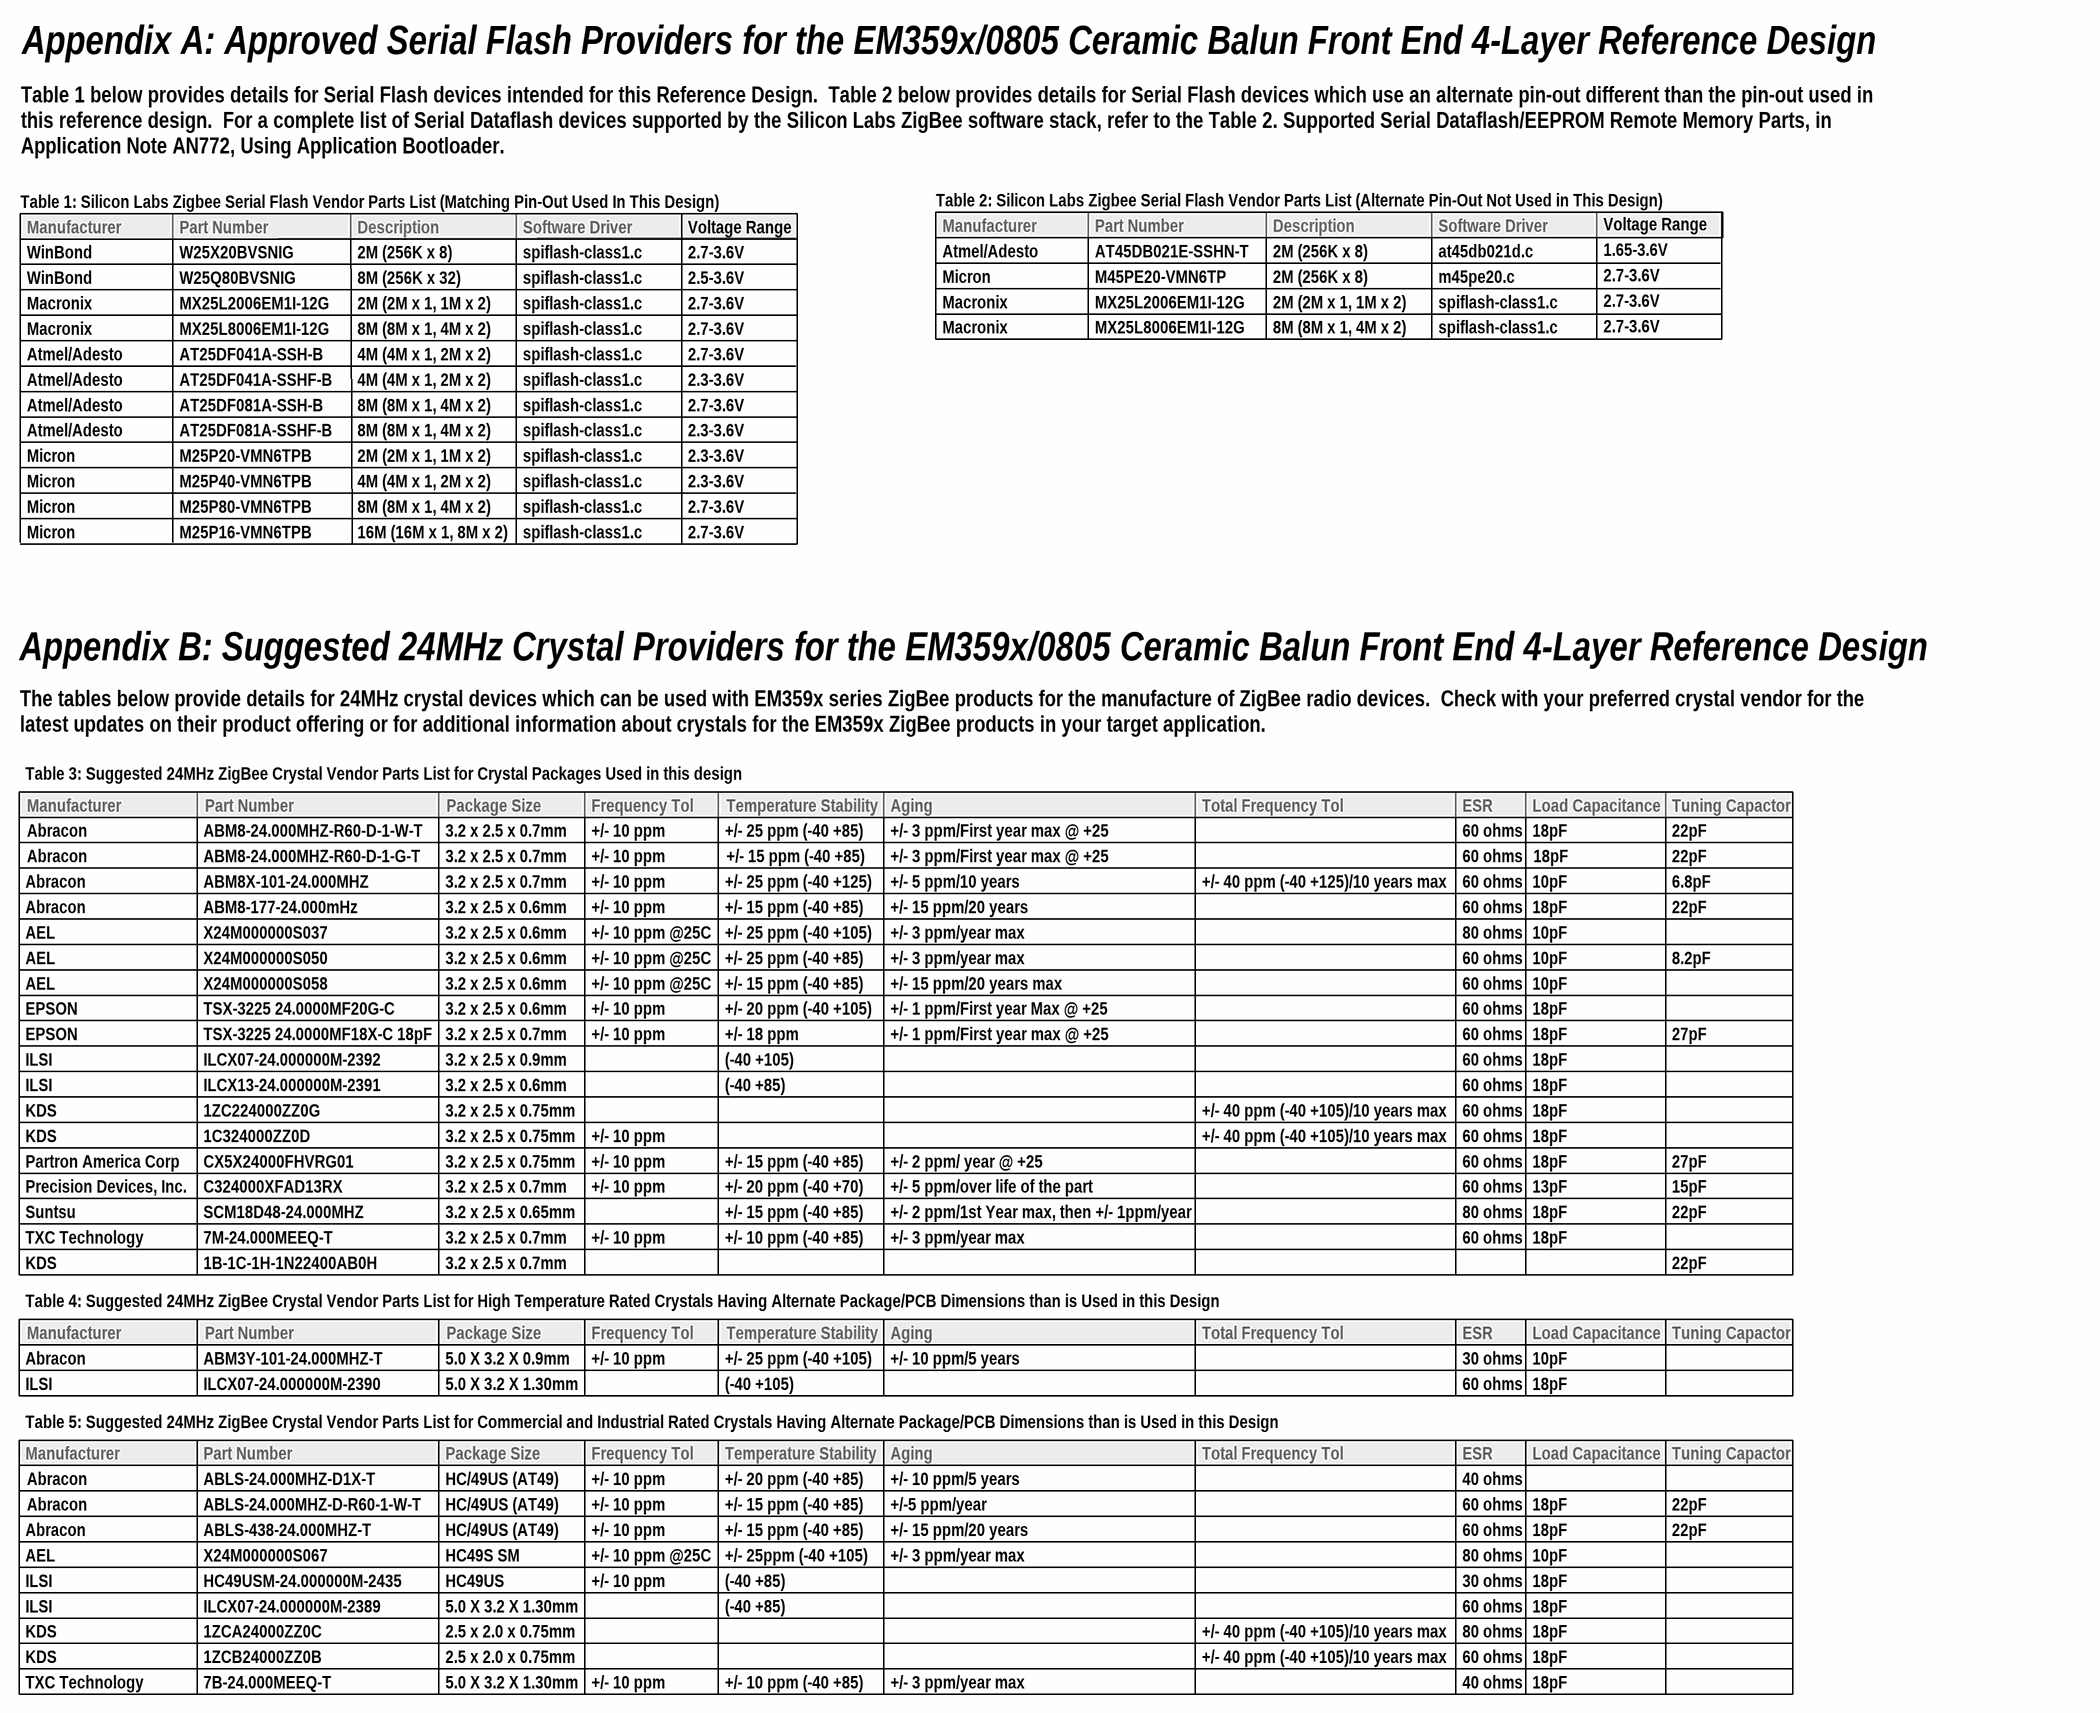
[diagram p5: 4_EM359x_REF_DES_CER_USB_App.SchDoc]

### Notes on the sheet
- Appendix A: Approved Serial Flash Providers for the EM359x/0805 Ceramic Balun Front End 4-Layer Reference Design
- Table 1 below provides details for Serial Flash devices intended for this Reference Design.  Table 2 below provides details for Serial Flash devices which use an alternate pin-out different than the pin-out used in this reference design.  For a complete list of Serial Dataflash devices supported by the Silicon Labs ZigBee software stack, refer to the Table 2. Supported Serial Dataflash/EEPROM Remote Memory Parts, in Application Note AN772, Using Application Bootloader.
- Table 1: Silicon Labs Zigbee Serial Flash Vendor Parts List (Matching Pin-Out Used In This Design)
- Table 2: Silicon Labs Zigbee Serial Flash Vendor Parts List (Alternate Pin-Out Not Used in This Design)
- Manufacturer
- WinBond
- Part Number
- W25X20BVSNIG
- 2M (256K x 8)
- Description
- Software Driver
- spiflash-class1.c
- Voltage Range
- 2.7-3.6V
- Atmel/Adesto
- Micron
- AT45DB021E-SSHN-T
- M45PE20-VMN6TP
- at45db021d.c
- m45pe20.c
- 1.65-3.6V
- Macronix
- W25Q80BVSNIG
- MX25L2006EM1I-12G
- MX25L8006EM1I-12G
- 8M (256K x 32)
- 2M (2M x 1, 1M x 2)
- 8M (8M x 1, 4M x 2)
- 2.5-3.6V
- AT25DF041A-SSH-B
- AT25DF041A-SSHF-B
- 4M (4M x 1, 2M x 2)
- 2.3-3.6V
- AT25DF081A-SSH-B
- M25P20-VMN6TPB
- AT25DF081A-SSHF-B
- M25P40-VMN6TPB
- M25P80-VMN6TPB
- M25P16-VMN6TPB
- 16M (16M x 1, 8M x 2)
- Appendix B: Suggested 24MHz Crystal Providers for the EM359x/0805 Ceramic Balun Front End 4-Layer Reference Design
- The tables below provide details for 24MHz crystal devices which can be used with EM359x series ZigBee products for the manufacture of ZigBee radio devices.  Check with your preferred crystal vendor for the latest updates on their product offering or for additional information about crystals for the EM359x ZigBee products in your target application.
- Table 3: Suggested 24MHz ZigBee Crystal Vendor Parts List for Crystal Packages Used in this design
- Abracon
- ABM8-24.000MHZ-R60-D-1-W-T
- 3.2 x 2.5 x 0.7mm
- Package Size
- Frequency Tol
- +/- 10 ppm
- +/- 25 ppm (-40 +85)
- Temperature Stability
- Aging
- +/- 3 ppm/First year max @ +25
- Total Frequency Tol
- ESR
- 60 ohms
- Load Capacitance
- 18pF
- Tuning Capactor
- 22pF
- ABM8-24.000MHZ-R60-D-1-G-T
- ABM8X-101-24.000MHZ
- ABM8-177-24.000mHz
- 3.2 x 2.5 x 0.6mm
- +/- 25 ppm (-40 +125)
- +/- 15 ppm (-40 +85)
- +/- 5 ppm/10 years
- +/- 15 ppm/20 years
- +/- 40 ppm (-40 +125)/10 years max
- 10pF
- 6.8pF
- AEL
- X24M000000S037
- X24M000000S050
- +/- 10 ppm @25C
- +/- 25 ppm (-40 +105)
- +/- 3 ppm/year max
- 80 ohms
- 8.2pF
- EPSON
- TSX-3225 24.0000MF18X-C 18pF
- TSX-3225 24.0000MF20G-C
- X24M000000S058
- +/- 18 ppm
- +/- 20 ppm (-40 +105)
- +/- 1 ppm/First year max @ +25
- +/- 1 ppm/First year Max @ +25
- +/- 15 ppm/20 years max
- 27pF
- ILSI
- ILCX07-24.000000M-2392
- ILCX13-24.000000M-2391
- 3.2 x 2.5 x 0.9mm
- (-40 +105)
- (-40 +85)
- Partron America Corp
- KDS
- 1ZC224000ZZ0G
- 1C324000ZZ0D
- CX5X24000FHVRG01
- 3.2 x 2.5 x 0.75mm
- +/- 2 ppm/ year @ +25
- +/- 40 ppm (-40 +105)/10 years max
- Suntsu
- Precision Devices, Inc.
- SCM18D48-24.000MHZ
- C324000XFAD13RX
- 3.2 x 2.5 x 0.65mm
- +/- 20 ppm (-40 +70)
- +/- 2 ppm/1st Year max, then +/- 1ppm/year
- +/- 5 ppm/over life of the part
- 13pF
- 15pF
- TXC Technology
- 7M-24.000MEEQ-T
- 1B-1C-1H-1N22400AB0H
- +/- 10 ppm (-40 +85)
- Table 4: Suggested 24MHz ZigBee Crystal Vendor Parts List for High Temperature Rated Crystals Having Alternate Package/PCB Dimensions than is Used in this Design
- ABM3Y-101-24.000MHZ-T
- 5.0 X 3.2 X 0.9mm
- +/- 10 ppm/5 years
- 30 ohms
- ILCX07-24.000000M-2390
- 5.0 X 3.2 X 1.30mm
- Table 5: Suggested 24MHz ZigBee Crystal Vendor Parts List for Commercial and Industrial Rated Crystals Having Alternate Package/PCB Dimensions than is Used in this Design
- ABLS-24.000MHZ-D1X-T
- HC/49US (AT49)
- +/- 20 ppm (-40 +85)
- 40 ohms
- ABLS-24.000MHZ-D-R60-1-W-T
- ABLS-438-24.000MHZ-T
- +/-5 ppm/year
- ILCX07-24.000000M-2389
- X24M000000S067
- HC49USM-24.000000M-2435
- HC49S SM
- HC49US
- +/- 25ppm (-40 +105)
- 1ZCA24000ZZ0C
- 1ZCB24000ZZ0B
- 2.5 x 2.0 x 0.75mm
- 7B-24.000MEEQ-T

## Sheet 5_EM359x_REF_DES_CER_USB_Rev_Notes.SchDoc: EM359x/0805 Ceramic Balun W/USB Reference Design
size C; Organization: MCU & Wireless WMN Support; Address1: 343 Congress Street, 4th Fl,; Address2: Boston, MA 02210, USA; Address3: www.silabs.com; Address4: 617-951-0200; DocumentNumber: 130-0859-001; Revision: A0; SheetNumber: 5; SheetTotal: 5; SheetSize: C
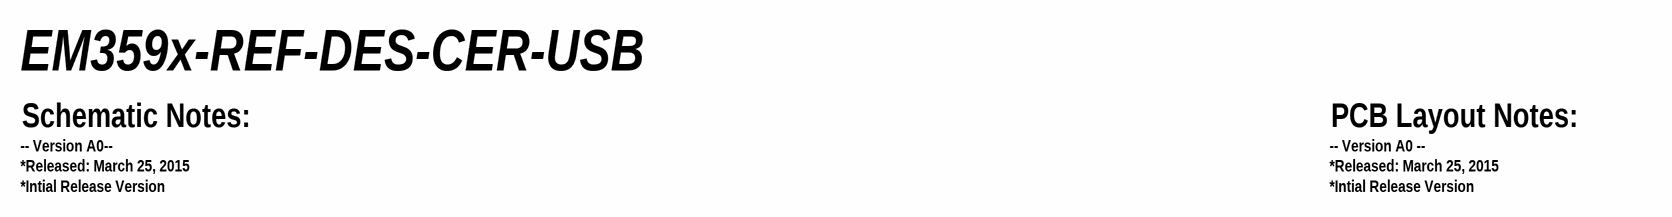
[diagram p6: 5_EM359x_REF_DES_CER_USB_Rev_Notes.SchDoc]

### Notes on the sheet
- EM359x-REF-DES-CER-USB
- -- Version A0--
- *Released: March 25, 2015
- Schematic Notes:
- -- Version A0 --
- PCB Layout Notes:
- *Intial Release Version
